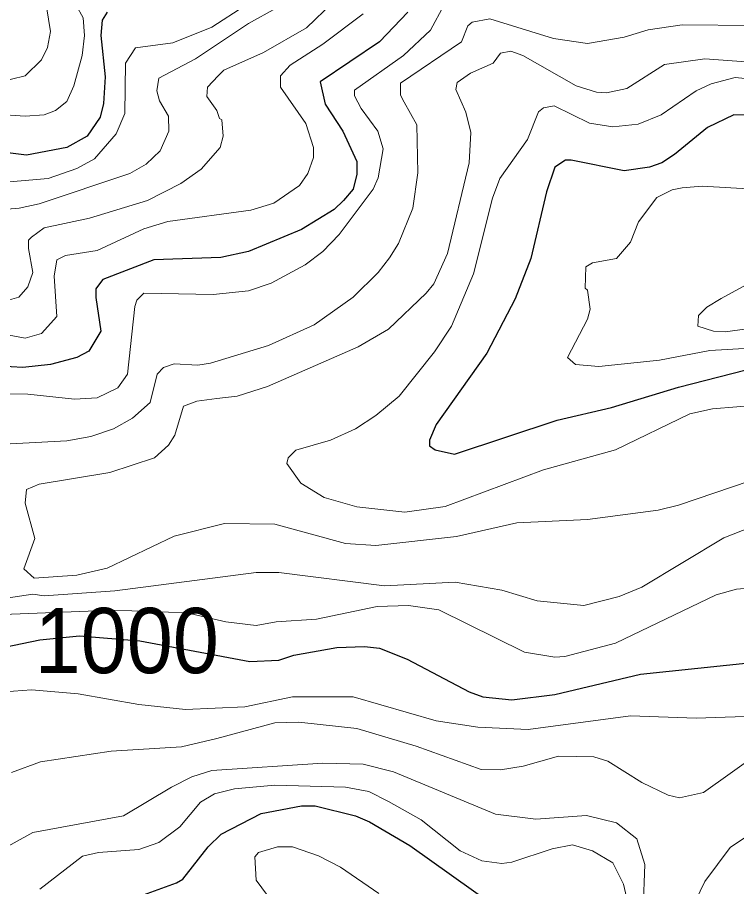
# Model space of a CAD drawing. Extents: x 423 to 448.8, y 7456.3 to 7484.
# Drawn here: x 433.707 to 434.59, y 7469.783 to 7470.849 of the extents above; entities that cross this region are included whole.
import ezdxf
from ezdxf.enums import TextEntityAlignment as Align

# ---------------------------------------------------------------- set-up
doc = ezdxf.new("R2010")
doc.units = 0
doc.header["$LTSCALE"] = 0.032
doc.layers.add('1', color=7, linetype='Continuous', lineweight=25)
doc.layers.add('2', color=7, linetype='Continuous', lineweight=13)
doc.layers.add('61', color=7, linetype='Continuous')

msp = doc.modelspace()

# ---------------------------------------------------------------- linework, layer by layer
at = {"layer": '1'}
for points in [[(433.8176, 7470.8556), (433.8114, 7470.8455), (433.8099, 7470.827), (433.8153, 7470.776), (433.813, 7470.7435), (433.8091, 7470.7265), (433.7929, 7470.7032), (433.7682, 7470.6893), (433.7187, 7470.68), (433.6692, 7470.6862)], [(434.1866, 7470.8556), (434.1518, 7470.8192), (434.0791, 7470.7698), (434.0852, 7470.7427), (434.1069, 7470.7094), (434.1239, 7470.6723), (434.1239, 7470.6569), (434.1193, 7470.6383), (434.1077, 7470.6244), (434.0961, 7470.6135), (434.0559, 7470.5888), (433.9909, 7470.5617), (433.9569, 7470.5547), (433.8749, 7470.5516)], [(434.619, 7470.7288), (434.5865, 7470.7295), (434.554, 7470.7141), (434.5138, 7470.6808), (434.4983, 7470.6708), (434.4828, 7470.6653), (434.4519, 7470.6607), (434.3869, 7470.6739), (434.3799, 7470.6739), (434.3668, 7470.6653), (434.3568, 7470.6352), (434.3374, 7470.5532), (434.3181, 7470.5037), (434.2833, 7470.4372), (434.2214, 7470.3498), (434.2129, 7470.3305)], [(433.8749, 7470.5516), (433.8122, 7470.5277), (433.8083, 7470.5223), (433.8037, 7470.516), (433.8037, 7470.5053), (433.8099, 7470.4642), (433.7952, 7470.4395), (433.7805, 7470.4317), (433.7481, 7470.4233), (433.714, 7470.4194), (433.6135, 7470.4255)], [(434.2129, 7470.3305), (434.2129, 7470.3235), (434.2199, 7470.3188), (434.2438, 7470.3134), (434.3699, 7470.3552), (434.4364, 7470.3707), (434.5184, 7470.3954), (434.6174, 7470.4209)], [(433.6815, 7470.0744), (433.7349, 7470.0855), (433.7835, 7470.0905), (433.8575, 7470.0844), (433.9925, 7470.059), (434.028, 7470.0605), (434.0466, 7470.0667), (434.0992, 7470.076), (434.1332, 7470.0775), (434.1518, 7470.0752), (434.1858, 7470.062), (434.2616, 7470.0218), (434.2786, 7470.0156), (434.3142, 7470.0118), (434.3668, 7470.0187), (434.472, 7470.0435), (434.6128, 7470.0582)], [(433.8532, 7469.7697), (433.9027, 7469.7874), (433.9105, 7469.7921), (433.9414, 7469.8315), (433.9576, 7469.847), (434.0064, 7469.8726), (434.0559, 7469.8818), (434.0729, 7469.8818), (434.1224, 7469.8695), (434.1394, 7469.8625), (434.1889, 7469.8331), (434.291, 7469.7604)]]:
    msp.add_lwpolyline(points, dxfattribs=at)
at = {"layer": '2'}
for points in [[(434.2477, 7470.8958), (434.2144, 7470.8332), (434.1812, 7470.8023), (434.1209, 7470.7597), (434.1209, 7470.7528), (434.1294, 7470.7373), (434.1495, 7470.7094), (434.1564, 7470.6877), (434.1502, 7470.6522), (434.144, 7470.6383), (434.1023, 7470.5826), (434.0822, 7470.5617), (434.0605, 7470.5454), (434.0188, 7470.523), (433.9909, 7470.5137), (433.9476, 7470.5091), (433.8625, 7470.5106), (433.854, 7470.5021), (433.8517, 7470.4944), (433.8424, 7470.4116), (433.8308, 7470.3946), (433.8053, 7470.3822), (433.7774, 7470.3807), (433.7202, 7470.3869), (433.663, 7470.3877)], [(433.7411, 7470.875), (433.748, 7470.8317), (433.7442, 7470.8123), (433.7372, 7470.7968), (433.7171, 7470.7775), (433.6831, 7470.769)], [(434.0945, 7470.8672), (434.0621, 7470.8363), (434.0095, 7470.8061), (433.9607, 7470.7844), (433.9538, 7470.7775), (433.9406, 7470.7636), (433.9399, 7470.752), (433.9522, 7470.735), (433.9553, 7470.7249), (433.9584, 7470.7234), (433.96, 7470.7033), (433.9561, 7470.6893), (433.9329, 7470.663), (433.9081, 7470.6452), (433.8672, 7470.6243), (433.796, 7470.6027), (433.7403, 7470.5911), (433.7248, 7470.5795), (433.7209, 7470.5756), (433.7209, 7470.5656), (433.7264, 7470.5362), (433.7202, 7470.5184), (433.7093, 7470.506), (433.6745, 7470.496)], [(433.7797, 7470.8641), (433.7883, 7470.8486), (433.7898, 7470.827), (433.7867, 7470.8023), (433.7766, 7470.7651), (433.7681, 7470.7458), (433.7542, 7470.7349), (433.7403, 7470.7295), (433.7171, 7470.728), (433.68, 7470.7303)], [(433.9863, 7470.8634), (433.9461, 7470.837), (433.8981, 7470.8177), (433.8524, 7470.8115), (433.8401, 7470.793), (433.8393, 7470.7311), (433.8285, 7470.7064), (433.8022, 7470.6754), (433.7805, 7470.6638), (433.745, 7470.6514), (433.6452, 7470.6429)], [(434.0249, 7470.8602), (433.9909, 7470.8417), (433.9259, 7470.7984), (433.881, 7470.7744), (433.8787, 7470.7589), (433.8818, 7470.7466), (433.8927, 7470.728), (433.8934, 7470.7094), (433.8826, 7470.6855), (433.8656, 7470.6692), (433.8455, 7470.6576), (433.7341, 7470.6205), (433.7094, 7470.615), (433.6699, 7470.6119)], [(434.1317, 7470.8533), (434.0822, 7470.8161), (434.042, 7470.7906), (434.0303, 7470.7775), (434.0303, 7470.7636), (434.0613, 7470.7187), (434.0706, 7470.6893), (434.0706, 7470.677), (434.0636, 7470.6576), (434.0535, 7470.6429), (434.0219, 7470.6212), (433.994, 7470.6127), (433.8919, 7470.5988), (433.8625, 7470.5895), (433.8053, 7470.5632), (433.7666, 7470.5571)], [(433.6676, 7470.3243), (433.7682, 7470.3296), (433.7976, 7470.3351), (433.8254, 7470.3444), (433.8486, 7470.3575), (433.8703, 7470.3768), (433.8788, 7470.4116), (433.8865, 7470.4194), (433.8997, 7470.424), (433.929, 7470.4225), (433.9445, 7470.4248), (434.0157, 7470.4464), (434.0714, 7470.472), (434.1193, 7470.506), (434.1502, 7470.5361), (434.1641, 7470.554), (434.175, 7470.5718), (434.1928, 7470.6151), (434.1989, 7470.6584), (434.1974, 7470.7172), (434.1819, 7470.745), (434.1774, 7470.7536), (434.1773, 7470.7682), (434.2523, 7470.8192), (434.2601, 7470.8386), (434.2655, 7470.8432), (434.2871, 7470.8471), (434.3653, 7470.8231), (434.407, 7470.8169), (434.4519, 7470.8247), (434.4813, 7470.8339), (434.5231, 7470.8401), (434.6112, 7470.8393)], [(434.6128, 7470.7937), (434.5509, 7470.7984), (434.5014, 7470.7914), (434.455, 7470.762), (434.4302, 7470.7566), (434.4179, 7470.7574), (434.3931, 7470.7651), (434.3274, 7470.8023), (434.3127, 7470.8076), (434.3003, 7470.8053), (434.291, 7470.7929), (434.2632, 7470.7806), (434.2469, 7470.769), (434.2454, 7470.7605), (434.2577, 7470.7327), (434.2639, 7470.7079), (434.2616, 7470.6708), (434.2353, 7470.5594), (434.2183, 7470.5223), (434.209, 7470.5106), (434.1626, 7470.4665), (434.1255, 7470.4449), (434.0141, 7470.3962), (433.977, 7470.3846), (433.9522, 7470.3815), (433.9275, 7470.3784), (433.9112, 7470.3722), (433.9004, 7470.3366), (433.8927, 7470.3243), (433.8757, 7470.3088), (433.8208, 7470.291), (433.7341, 7470.2763), (433.7186, 7470.2701), (433.7171, 7470.2531), (433.7287, 7470.2098), (433.7155, 7470.1727), (433.7279, 7470.161), (433.7805, 7470.1649), (433.8177, 7470.1734), (433.8997, 7470.2129), (433.9615, 7470.2283), (434.0234, 7470.2276), (434.11, 7470.2036), (434.1472, 7470.2013), (434.2462, 7470.2121), (434.3204, 7470.2291), (434.407, 7470.233), (434.4937, 7470.2446), (434.5184, 7470.2508), (434.6283, 7470.2879)], [(434.3529, 7470.738), (434.366, 7470.7404), (434.4093, 7470.7195), (434.438, 7470.7148), (434.4689, 7470.7179), (434.4975, 7470.7295), (434.5401, 7470.7589), (434.5586, 7470.7674), (434.588, 7470.7752), (434.6205, 7470.7721)], [(434.6499, 7470.3761), (434.5602, 7470.3691), (434.5323, 7470.3629), (434.4411, 7470.3188), (434.3529, 7470.2941), (434.2322, 7470.2492), (434.1827, 7470.2422), (434.124, 7470.2485), (434.0837, 7470.26), (434.0551, 7470.2778), (434.0381, 7470.3018), (434.0396, 7470.3088), (434.0489, 7470.3181), (434.0915, 7470.3304), (434.1224, 7470.3443), (434.1471, 7470.3606), (434.1758, 7470.3846), (434.2191, 7470.4387), (434.2399, 7470.4704), (434.267, 7470.5346), (434.2902, 7470.6275), (434.2995, 7470.6514), (434.3335, 7470.6994), (434.3467, 7470.7334), (434.3529, 7470.738)], [(434.6112, 7470.6383), (434.5478, 7470.6421), (434.5231, 7470.6398), (434.5107, 7470.6375), (434.4921, 7470.6282), (434.4697, 7470.5981), (434.4596, 7470.5733), (434.4426, 7470.5532), (434.4132, 7470.5478), (434.4047, 7470.5431), (434.4039, 7470.5168), (434.407, 7470.5145), (434.4101, 7470.4913), (434.407, 7470.479), (434.3823, 7470.4317), (434.3923, 7470.4232), (434.421, 7470.4209), (434.4952, 7470.4286), (434.5571, 7470.4403), (434.6066, 7470.4433)], [(433.7666, 7470.5571), (433.7558, 7470.5517), (433.7527, 7470.5316), (433.7558, 7470.482), (433.7372, 7470.4611), (433.7171, 7470.4557), (433.6444, 7470.4689)], [(434.6468, 7470.5454), (434.571, 7470.5044), (434.5532, 7470.4936), (434.5432, 7470.4835), (434.5424, 7470.4704), (434.5617, 7470.4642), (434.5757, 7470.4634), (434.7133, 7470.482)], [(434.6313, 7470.233), (434.5741, 7470.2105), (434.4736, 7470.1502), (434.4457, 7470.1386), (434.4024, 7470.1278), (434.3452, 7470.1332), (434.3019, 7470.1463), (434.2446, 7470.1564), (434.158, 7470.1517), (434.028, 7470.168), (434.0002, 7470.168), (433.8269, 7470.1456), (433.7403, 7470.1394), (433.7264, 7470.1417), (433.6552, 7470.1309)], [(433.6166, 7470.0914), (433.6465, 7470.1105), (433.69, 7470.1165), (433.8252, 7470.1218), (433.9153, 7470.1188), (433.9631, 7470.1077), (434.0002, 7470.103), (434.025, 7470.1077), (434.0745, 7470.1108), (434.1487, 7470.1263), (434.1874, 7470.1278), (434.2245, 7470.1224), (434.3297, 7470.0706), (434.3668, 7470.0643), (434.3792, 7470.0651), (434.4411, 7470.0814), (434.5648, 7470.1409), (434.5896, 7470.1479), (434.6391, 7470.1518)], [(433.68, 7470.0211), (433.7248, 7470.0241), (433.7821, 7470.0195), (433.8563, 7470.0063), (433.9136, 7470.0002), (433.9863, 7470.0032), (434.0451, 7470.0156), (434.1193, 7470.0156), (434.2214, 7469.9862), (434.2725, 7469.9785), (434.3343, 7469.9754), (434.4596, 7469.9924), (434.5401, 7469.9893), (434.6236, 7469.9924)], [(433.7001, 7469.9228), (433.7357, 7469.9359), (433.8223, 7469.9491), (433.9089, 7469.9545), (433.9522, 7469.9646), (434.0234, 7469.9839), (434.0528, 7469.9847), (434.124, 7469.9769), (434.1967, 7469.9553), (434.2763, 7469.9267), (434.3003, 7469.9259), (434.3281, 7469.9305), (434.3715, 7469.9429), (434.4148, 7469.9421), (434.4317, 7469.9367), (434.4736, 7469.9104), (434.506, 7469.895), (434.52, 7469.8919), (434.5494, 7469.8981), (434.6174, 7469.9468)], [(433.6537, 7469.8091), (433.7264, 7469.8494), (433.8378, 7469.8695), (433.8966, 7469.905), (433.9213, 7469.9174), (433.9461, 7469.9252), (434.0822, 7469.9344), (434.1317, 7469.9329), (434.1688, 7469.9236), (434.2941, 7469.8718), (434.3436, 7469.8656), (434.4055, 7469.8702), (434.4426, 7469.8609), (434.4673, 7469.8416), (434.4774, 7469.8099), (434.4751, 7469.755)], [(433.7349, 7469.7797), (433.7875, 7469.82), (433.8068, 7469.8246), (433.8563, 7469.8284), (433.8811, 7469.8369), (433.9066, 7469.8563), (433.9321, 7469.8865), (433.9492, 7469.8965), (433.9739, 7469.9027), (434.0234, 7469.9073), (434.11, 7469.905), (434.1386, 7469.8996), (434.1626, 7469.8872), (434.2028, 7469.8648), (434.2508, 7469.8269), (434.2771, 7469.8145), (434.3019, 7469.8114), (434.3142, 7469.813), (434.3637, 7469.8292), (434.3885, 7469.8339), (434.4132, 7469.8269), (434.438, 7469.8122), (434.4511, 7469.7859), (434.4596, 7469.7488)], [(434.612, 7469.8509), (434.5818, 7469.8307), (434.5509, 7469.789), (434.5338, 7469.7534)], [(434.151, 7469.7743), (434.1038, 7469.8068), (434.0767, 7469.8207), (434.045, 7469.8315), (434.0265, 7469.8315), (434.0032, 7469.8246), (433.9986, 7469.8192), (434.0002, 7469.7906), (434.0141, 7469.772)]]:
    msp.add_lwpolyline(points, dxfattribs=at)

# ---------------------------------------------------------------- texts
at = {"layer": '61', "width": 0.95}
msp.add_text('1000', height=0.08, dxfattribs=at).set_placement((433.8416, 7470.0447), align=Align.CENTER)

doc.saveas('drawing.dxf')
